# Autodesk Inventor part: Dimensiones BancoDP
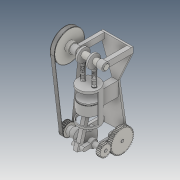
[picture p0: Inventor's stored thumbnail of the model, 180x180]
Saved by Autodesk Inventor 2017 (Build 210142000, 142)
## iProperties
Created: 2019-09
Part Number: Dimensiones BancoDP
Material: Generic
Document SubType Name: Modeling
Designer: user
Density: 1 g/cm^3
Appearance: Default
Author: user
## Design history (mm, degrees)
derived "Ensamble.iam"
body "Solid1"
node "Cigueñal.ipt:1"
node "Synchronous Belts Transmission:1::Synchronous Belt:1"
body "Solid2"
node "Synchronous Belts Transmission:1::Synchronous Pulley1:1"
body "Solid3"
node "Synchronous Belts Transmission:1::Synchronous Pulley2:1"
body "Solid4"
node "Bloque del motor.ipt:1"
body "Solid5"
node "Pistón.ipt:1"
body "Solid6"
node "Biela.ipt:1"
body "Solid7"
node "Válvula.ipt:1"
body "Solid8"
node "Válvula.ipt:2"
body "Solid9"
node "Shaft:1::Shaft:1"
body "Solid10"
node "Leva.ipt:1"
body "Solid11"
node "Leva.ipt:2"
body "Solid12"
node "Spur Gears:1::Spur Gear1:1"
body "Solid13"
node "Spur Gears:1::Spur Gear2:1"
body "Solid14"
node "Resorte.ipt:1"
body "Solid15"
node "Resorte.ipt:2"
body "Solid16"
